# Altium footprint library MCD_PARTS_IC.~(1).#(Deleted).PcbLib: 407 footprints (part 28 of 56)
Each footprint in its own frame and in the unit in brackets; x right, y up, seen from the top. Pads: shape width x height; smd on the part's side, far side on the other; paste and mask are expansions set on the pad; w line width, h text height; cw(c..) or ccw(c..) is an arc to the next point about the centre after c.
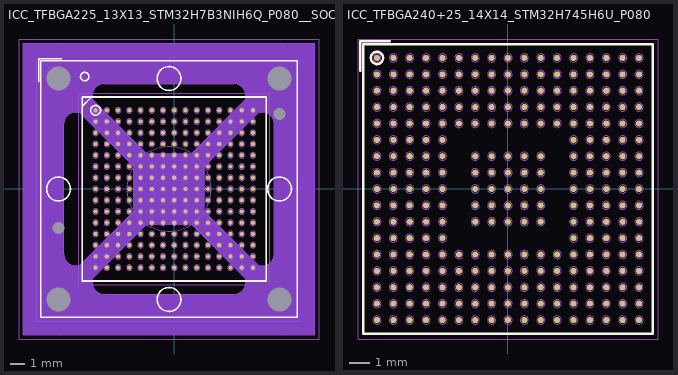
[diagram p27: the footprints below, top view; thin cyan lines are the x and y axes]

## ICC_TFBGA225_13X13_STM32H7B3NIH6Q_P080__SOCKET_IRONWOOD_CS1222291MF_REV-A_WITHOUT-3D-SOCKET [mm] "MCD-01577"
height 1.2
pads (231):
  round 0.3 smd mask+0.05: A1(-5.6,5.6) A2(-4.8,5.6) A3(-4,5.6) A4(-3.2,5.6) A5(-2.4,5.6) A6(-1.6,5.6) A7(-0.8,5.6) A8(0,5.6) A9(0.8,5.6) A10(1.6,5.6) A11(2.4,5.6) A12(3.2,5.6) A13(4,5.6) A14(4.8,5.6) A15(5.6,5.6) B1(-5.6,4.8) B2(-4.8,4.8) B3(-4,4.8) B4(-3.2,4.8) B5(-2.4,4.8) B6(-1.6,4.8) B7(-0.8,4.8) B8(0,4.8) B9(0.8,4.8) B10(1.6,4.8) B11(2.4,4.8) B12(3.2,4.8) B13(4,4.8) B14(4.8,4.8) B15(5.6,4.8) C1(-5.6,4) C2(-4.8,4) C3(-4,4) C4(-3.2,4) C5(-2.4,4) C6(-1.6,4) C7(-0.8,4) C8(0,4) C9(0.8,4) C10(1.6,4) C11(2.4,4) C12(3.2,4) C13(4,4) C14(4.8,4) C15(5.6,4) D1(-5.6,3.2) D2(-4.8,3.2) D3(-4,3.2) D4(-3.2,3.2) D5(-2.4,3.2) D6(-1.6,3.2) D7(-0.8,3.2) D8(0,3.2) D9(0.8,3.2) D10(1.6,3.2) D11(2.4,3.2) D12(3.2,3.2) D13(4,3.2) D14(4.8,3.2) D15(5.6,3.2) E1(-5.6,2.4) E2(-4.8,2.4) E3(-4,2.4) E4(-3.2,2.4) E5(-2.4,2.4) E6(-1.6,2.4) E7(-0.8,2.4) E8(0,2.4) E9(0.8,2.4) E10(1.6,2.4) E11(2.4,2.4) E12(3.2,2.4) E13(4,2.4) E14(4.8,2.4) E15(5.6,2.4) F1(-5.6,1.6) F2(-4.8,1.6) F3(-4,1.6) F4(-3.2,1.6) F5(-2.4,1.6) F6(-1.6,1.6) F7(-0.8,1.6) F8(0,1.6) F9(0.8,1.6) F10(1.6,1.6) F11(2.4,1.6) F12(3.2,1.6) F13(4,1.6) F14(4.8,1.6) F15(5.6,1.6) G1(-5.6,0.8) G2(-4.8,0.8) G3(-4,0.8) G4(-3.2,0.8) G5(-2.4,0.8) G6(-1.6,0.8) G7(-0.8,0.8) G8(0,0.8) G9(0.8,0.8) G10(1.6,0.8) G11(2.4,0.8) G12(3.2,0.8) G13(4,0.8) G14(4.8,0.8) G15(5.6,0.8) H1(-5.6,0) H2(-4.8,0) H3(-4,0) H4(-3.2,0) H5(-2.4,0) H6(-1.6,0) H7(-0.8,0) H8(0,0) H9(0.8,0) H10(1.6,0) H11(2.4,0) H12(3.2,0) H13(4,0) H14(4.8,0) H15(5.6,0) J1(-5.6,-0.8) J2(-4.8,-0.8) J3(-4,-0.8) J4(-3.2,-0.8) J5(-2.4,-0.8) J6(-1.6,-0.8) J7(-0.8,-0.8) J8(0,-0.8) J9(0.8,-0.8) J10(1.6,-0.8) J11(2.4,-0.8) J12(3.2,-0.8) J13(4,-0.8) J14(4.8,-0.8) J15(5.6,-0.8) K1(-5.6,-1.6) K2(-4.8,-1.6) K3(-4,-1.6) K4(-3.2,-1.6) K5(-2.4,-1.6) K6(-1.6,-1.6) K7(-0.8,-1.6) K8(0,-1.6) K9(0.8,-1.6) K10(1.6,-1.6) K11(2.4,-1.6) K12(3.2,-1.6) K13(4,-1.6) K14(4.8,-1.6) K15(5.6,-1.6) L1(-5.6,-2.4) L2(-4.8,-2.4) L3(-4,-2.4) L4(-3.2,-2.4) L5(-2.4,-2.4) L6(-1.6,-2.4) L7(-0.8,-2.4) L8(0,-2.4) L9(0.8,-2.4) L10(1.6,-2.4) L11(2.4,-2.4) L12(3.2,-2.4) L13(4,-2.4) L14(4.8,-2.4) L15(5.6,-2.4) M1(-5.6,-3.2) M2(-4.8,-3.2) M3(-4,-3.2) M4(-3.2,-3.2) M5(-2.4,-3.2) M6(-1.6,-3.2) M7(-0.8,-3.2) M8(0,-3.2) M9(0.8,-3.2) M10(1.6,-3.2) M11(2.4,-3.2) M12(3.2,-3.2) M13(4,-3.2) M14(4.8,-3.2) M15(5.6,-3.2) N1(-5.6,-4) N2(-4.8,-4) N3(-4,-4) N4(-3.2,-4) N5(-2.4,-4) N6(-1.6,-4) N7(-0.8,-4) N8(0,-4) N9(0.8,-4) N10(1.6,-4) N11(2.4,-4) N12(3.2,-4) N13(4,-4) N14(4.8,-4) N15(5.6,-4) P1(-5.6,-4.8) P2(-4.8,-4.8) P3(-4,-4.8) P4(-3.2,-4.8) P5(-2.4,-4.8) P6(-1.6,-4.8) P7(-0.8,-4.8) P8(0,-4.8) P9(0.8,-4.8) P10(1.6,-4.8) P11(2.4,-4.8) P12(3.2,-4.8) P13(4,-4.8) P14(4.8,-4.8) P15(5.6,-4.8) R1(-5.6,-5.6) R2(-4.8,-5.6) R3(-4,-5.6) R4(-3.2,-5.6) R5(-2.4,-5.6) R6(-1.6,-5.6) R7(-0.8,-5.6) R8(0,-5.6) R9(0.8,-5.6) R10(1.6,-5.6) R11(2.4,-5.6) R12(3.2,-5.6) R13(4,-5.6) R14(4.8,-5.6) R15(5.6,-5.6)
  round 0 hole 0.85 unplated mask+0.05: NPTH1(7.487,5.322) NPTH2(-8.238,-2.783)
  round 0 hole 1.71 unplated mask+0.05: PTH1(-8.238,7.862) PTH2(7.487,7.862) PTH3(7.487,-7.863) PTH4(-8.238,-7.863)
Bottom Layer keep-out:
  circle w0.01: c7.487,7.862 r2.5
  circle w0.01: c-8.238,7.862 r2.5
  circle w0.01: c-8.238,-7.863 r2.5
  circle w0.01: c7.487,-7.863 r2.5
  region: -0.376,0 -0.376,-2.5 1.224,-2.5 5.024,-6.3 5.04,-6.317 5.066,-6.356 5.084,-6.4 5.093,-6.446 5.094,-6.469 5.094,-6.63 5.09,-6.715 5.057,-6.883 4.991,-7.04 4.897,-7.182 4.776,-7.303 4.634,-7.397 4.477,-7.463 4.309,-7.496 4.224,-7.5 -0.376,-7.5 -0.376,-10.365 9.988,-10.365 9.988,10.365 -0.376,10.365 -0.376,7.5 4.224,7.5 4.309,7.496 4.477,7.463 4.634,7.397 4.776,7.303 4.897,7.182 4.991,7.04 5.057,6.883 5.09,6.715 5.094,6.63 5.094,6.469 5.093,6.446 5.084,6.4 5.066,6.356 5.04,6.317 5.024,6.3 1.224,2.5 -0.376,2.5 -0.376,0 2.124,0 2.124,1.6 5.924,5.4 5.941,5.416 5.98,5.442 6.024,5.46 6.07,5.469 6.093,5.47 6.254,5.47 6.339,5.466 6.507,5.433 6.664,5.367 6.806,5.273 6.927,5.152 7.021,5.01 7.087,4.853 7.12,4.685 7.124,4.6 7.124,-4.6 7.12,-4.685 7.087,-4.853 7.021,-5.01 6.927,-5.152 6.806,-5.273 6.664,-5.367 6.507,-5.433 6.339,-5.466 6.254,-5.47 6.093,-5.47 6.07,-5.469 6.024,-5.46 5.98,-5.442 5.941,-5.416 5.924,-5.4 2.124,-1.6 2.124,0
  region: -0.376,0 -0.376,2.5 -1.976,2.5 -5.776,6.3 -5.792,6.317 -5.818,6.356 -5.836,6.4 -5.845,6.446 -5.846,6.469 -5.846,6.63 -5.842,6.715 -5.809,6.883 -5.743,7.04 -5.649,7.182 -5.528,7.303 -5.386,7.397 -5.229,7.463 -5.061,7.496 -4.976,7.5 -0.376,7.5 -0.376,10.365 -10.74,10.365 -10.74,-10.365 -0.376,-10.365 -0.376,-7.5 -4.976,-7.5 -5.061,-7.496 -5.229,-7.463 -5.386,-7.397 -5.528,-7.303 -5.649,-7.182 -5.743,-7.04 -5.809,-6.883 -5.842,-6.715 -5.846,-6.63 -5.846,-6.469 -5.845,-6.446 -5.836,-6.4 -5.818,-6.356 -5.792,-6.317 -5.776,-6.3 -1.976,-2.5 -0.376,-2.5 -0.376,0 -2.876,0 -2.876,-1.6 -6.676,-5.4 -6.693,-5.416 -6.732,-5.442 -6.776,-5.46 -6.822,-5.469 -6.845,-5.47 -7.006,-5.47 -7.091,-5.466 -7.259,-5.433 -7.416,-5.367 -7.558,-5.273 -7.679,-5.152 -7.773,-5.01 -7.839,-4.853 -7.872,-4.685 -7.876,-4.6 -7.876,4.6 -7.872,4.685 -7.839,4.853 -7.773,5.01 -7.679,5.152 -7.558,5.273 -7.416,5.367 -7.259,5.433 -7.091,5.466 -7.006,5.47 -6.845,5.47 -6.822,5.469 -6.776,5.46 -6.732,5.442 -6.693,5.416 -6.676,5.4 -2.876,1.6 -2.876,0
Top Overlay:
  circle w0.12: c-6.375,8 r0.3
  circle w0.12: c-0.375,-7.863 r0.85
  circle w0.12: c7.487,0 r0.85
  circle w0.12: c-0.375,7.862 r0.85
  circle w0.12: c-8.238,0 r0.85
  circle w0.12: c-5.6,5.6 r0.35
  lines w0.12: -9.65,7.625 -9.65,9.275 -8,9.275 ; -6.55,5.895 -5.895,6.55 ; -9.5,-9.125 8.75,-9.125 8.75,9.125 -9.5,9.125 -9.5,-9.125 ; -6.55,-6.55 -6.55,6.55 6.55,6.55 6.55,-6.55 -6.55,-6.55
Bottom Overlay:
  lines w0.12: -10.75,-10.375 10,-10.375 10,10.375 -7.625,10.375 -10.75,10.375 -10.75,-10.375
M14-Top Assembly:
  drawing of 245 lines, arcs and shapes, not listed
  text "A1" at -5.85,5.425 h0.4
  text "'.Designator'" at -6.5,7.25 h0.75
M15-Bottom Assembly:
  lines w0.01: -2.891,1.615 -2.876,1.6 ; -2.891,1.615 -6.676,5.4 ccw(c-6.845,5.231) -6.845,5.47 -7.006,5.47 ccw(c-7.006,4.6) -7.876,4.6 -7.876,-4.6 ccw(c-7.006,-4.6) -7.006,-5.47 -6.845,-5.47 ccw(c-6.845,-5.231) -6.676,-5.4 -2.891,-1.615 -2.876,-1.6 -2.876,1.6 ; -2.891,1.615 -2.891,1.615 ; -2.876,1.6 -2.876,1.6 ; -1.991,-2.515 -1.991,-2.515 ; -1.991,-2.515 -5.776,-6.3 ccw(c-5.607,-6.469) -5.846,-6.469 -5.846,-6.63 ccw(c-4.976,-6.63) -4.976,-7.5 4.224,-7.5 ccw(c4.224,-6.63) 5.094,-6.63 5.094,-6.469 ccw(c4.855,-6.469) 5.024,-6.3 1.239,-2.515 1.224,-2.5 -1.976,-2.5 ; -1.991,-2.515 -1.976,-2.5 ; -1.976,-2.5 -1.976,-2.5 ; 1.224,2.5 1.239,2.515 ; 1.224,2.5 1.224,2.5 ; 1.224,2.5 -1.976,2.5 -1.991,2.515 -5.776,6.3 cw(c-5.607,6.469) -5.846,6.469 -5.846,6.63 cw(c-4.976,6.63) -4.976,7.5 4.224,7.5 cw(c4.224,6.63) 5.094,6.63 5.094,6.469 cw(c4.855,6.469) 5.024,6.3 1.239,2.515 ; 1.239,2.515 1.239,2.515 ; 2.124,-1.6 2.139,-1.615 ; 2.124,-1.6 2.124,-1.6 ; 2.124,-1.6 2.124,1.6 2.139,1.615 5.924,5.4 cw(c6.093,5.231) 6.093,5.47 6.254,5.47 cw(c6.254,4.6) 7.124,4.6 7.124,-4.6 cw(c6.254,-4.6) 6.254,-5.47 6.093,-5.47 cw(c6.093,-5.231) 5.924,-5.4 2.139,-1.615 ; 2.139,-1.615 2.139,-1.615 ; -10.74,-10.365 -10.74,10.365 9.99,10.365 9.99,-10.365 -10.74,-10.365
M16-Top Courtyard:
  lines w0.01: -9.8,-9.425 -9.8,8.5 -9.8,9.425 9.05,9.425 9.05,-9.425 -9.8,-9.425 ; -6.8,-6.8 6.8,-6.8 6.8,6.8 -6.8,6.8 -6.8,-6.8
M17-Bottom Courtyard:
  lines w0.01: -11.05,-10.675 10.3,-10.675 10.3,10.675 -11.05,10.675 -11.05,-10.675
3D body: height 0.36, standoff -0.04, extent 5.401,5.403 5.8,5.797
3D body: height 1.2, standoff 0.3, extent -6.55,-6.55 6.55,6.55
3D body: height 0.36, standoff -0.04, extent 4.601,5.403 5,5.797
3D body: height 0.36, standoff -0.04, extent 3.801,5.403 4.2,5.797
3D body: height 0.36, standoff -0.04, extent 3.001,5.403 3.4,5.797
3D body: height 0.36, standoff -0.04, extent 2.201,5.403 2.6,5.797
3D body: height 0.36, standoff -0.04, extent -1.799,5.403 -1.4,5.797
3D body: height 0.36, standoff -0.04, extent -0.999,5.403 -0.6,5.797
3D body: height 0.36, standoff -0.04, extent -0.199,5.403 0.2,5.797
3D body: height 0.36, standoff -0.04, extent 0.601,5.403 1,5.797
3D body: height 0.36, standoff -0.04, extent 1.401,5.403 1.8,5.797
3D body: height 0.36, standoff -0.04, extent -5.799,5.403 -5.4,5.797
3D body: height 0.36, standoff -0.04, extent -4.999,5.403 -4.6,5.797
3D body: height 0.36, standoff -0.04, extent -4.199,5.403 -3.8,5.797
3D body: height 0.36, standoff -0.04, extent -3.399,5.403 -3,5.797
3D body: height 0.36, standoff -0.04, extent -2.599,5.403 -2.2,5.797
3D body: height 0.36, standoff -0.04, extent -2.599,4.603 -2.2,4.997
3D body: height 0.36, standoff -0.04, extent -3.399,4.603 -3,4.997
3D body: height 0.36, standoff -0.04, extent -4.199,4.603 -3.8,4.997
3D body: height 0.36, standoff -0.04, extent -4.999,4.603 -4.6,4.997
3D body: height 0.36, standoff -0.04, extent -5.799,4.603 -5.4,4.997
3D body: height 0.36, standoff -0.04, extent 1.401,4.603 1.8,4.997
3D body: height 0.36, standoff -0.04, extent 0.601,4.603 1,4.997
3D body: height 0.36, standoff -0.04, extent -0.199,4.603 0.2,4.997
3D body: height 0.36, standoff -0.04, extent -0.999,4.603 -0.6,4.997
3D body: height 0.36, standoff -0.04, extent -1.799,4.603 -1.4,4.997
3D body: height 0.36, standoff -0.04, extent 2.201,4.603 2.6,4.997
3D body: height 0.36, standoff -0.04, extent 3.001,4.603 3.4,4.997
3D body: height 0.36, standoff -0.04, extent 3.801,4.603 4.2,4.997
3D body: height 0.36, standoff -0.04, extent 4.601,4.603 5,4.997
3D body: height 0.36, standoff -0.04, extent 5.401,4.603 5.8,4.997
3D body: height 0.36, standoff -0.04, extent -2.599,3.803 -2.2,4.197
3D body: height 0.36, standoff -0.04, extent -3.399,3.803 -3,4.197
3D body: height 0.36, standoff -0.04, extent -4.199,3.803 -3.8,4.197
3D body: height 0.36, standoff -0.04, extent -4.999,3.803 -4.6,4.197
3D body: height 0.36, standoff -0.04, extent -5.799,3.803 -5.4,4.197
3D body: height 0.36, standoff -0.04, extent 1.401,3.803 1.8,4.197
3D body: height 0.36, standoff -0.04, extent 0.601,3.803 1,4.197
3D body: height 0.36, standoff -0.04, extent -0.199,3.803 0.2,4.197
3D body: height 0.36, standoff -0.04, extent -0.999,3.803 -0.6,4.197
3D body: height 0.36, standoff -0.04, extent -1.799,3.803 -1.4,4.197
3D body: height 0.36, standoff -0.04, extent 2.201,3.803 2.6,4.197
3D body: height 0.36, standoff -0.04, extent 3.001,3.803 3.4,4.197
3D body: height 0.36, standoff -0.04, extent 3.801,3.803 4.2,4.197
3D body: height 0.36, standoff -0.04, extent 4.601,3.803 5,4.197
3D body: height 0.36, standoff -0.04, extent 5.401,3.803 5.8,4.197
3D body: height 0.36, standoff -0.04, extent -2.599,3.003 -2.2,3.397
3D body: height 0.36, standoff -0.04, extent -3.399,3.003 -3,3.397
3D body: height 0.36, standoff -0.04, extent -4.199,3.003 -3.8,3.397
3D body: height 0.36, standoff -0.04, extent -4.999,3.003 -4.6,3.397
3D body: height 0.36, standoff -0.04, extent -5.799,3.003 -5.4,3.397
3D body: height 0.36, standoff -0.04, extent 1.401,3.003 1.8,3.397
3D body: height 0.36, standoff -0.04, extent 0.601,3.003 1,3.397
3D body: height 0.36, standoff -0.04, extent -0.199,3.003 0.2,3.397
3D body: height 0.36, standoff -0.04, extent -0.999,3.003 -0.6,3.397
3D body: height 0.36, standoff -0.04, extent -1.799,3.003 -1.4,3.397
3D body: height 0.36, standoff -0.04, extent 2.201,3.003 2.6,3.397
3D body: height 0.36, standoff -0.04, extent 3.001,3.003 3.4,3.397
3D body: height 0.36, standoff -0.04, extent 3.801,3.003 4.2,3.397
3D body: height 0.36, standoff -0.04, extent 4.601,3.003 5,3.397
3D body: height 0.36, standoff -0.04, extent 5.401,3.003 5.8,3.397
3D body: height 0.36, standoff -0.04, extent -2.599,2.203 -2.2,2.597
3D body: height 0.36, standoff -0.04, extent -3.399,2.203 -3,2.597
3D body: height 0.36, standoff -0.04, extent -4.199,2.203 -3.8,2.597
3D body: height 0.36, standoff -0.04, extent -4.999,2.203 -4.6,2.597
3D body: height 0.36, standoff -0.04, extent -5.799,2.203 -5.4,2.597
3D body: height 0.36, standoff -0.04, extent 1.401,2.203 1.8,2.597
3D body: height 0.36, standoff -0.04, extent 0.601,2.203 1,2.597
3D body: height 0.36, standoff -0.04, extent -0.199,2.203 0.2,2.597
3D body: height 0.36, standoff -0.04, extent -0.999,2.203 -0.6,2.597
3D body: height 0.36, standoff -0.04, extent -1.799,2.203 -1.4,2.597
3D body: height 0.36, standoff -0.04, extent 2.201,2.203 2.6,2.597
3D body: height 0.36, standoff -0.04, extent 3.001,2.203 3.4,2.597
3D body: height 0.36, standoff -0.04, extent 3.801,2.203 4.2,2.597
3D body: height 0.36, standoff -0.04, extent 4.601,2.203 5,2.597
3D body: height 0.36, standoff -0.04, extent 5.401,2.203 5.8,2.597
3D body: height 0.36, standoff -0.04, extent -2.599,1.403 -2.2,1.797
3D body: height 0.36, standoff -0.04, extent -3.399,1.403 -3,1.797
3D body: height 0.36, standoff -0.04, extent -4.199,1.403 -3.8,1.797
3D body: height 0.36, standoff -0.04, extent -4.999,1.403 -4.6,1.797
3D body: height 0.36, standoff -0.04, extent -5.799,1.403 -5.4,1.797
3D body: height 0.36, standoff -0.04, extent 1.401,1.403 1.8,1.797
3D body: height 0.36, standoff -0.04, extent 0.601,1.403 1,1.797
3D body: height 0.36, standoff -0.04, extent -0.199,1.403 0.2,1.797
3D body: height 0.36, standoff -0.04, extent -0.999,1.403 -0.6,1.797
3D body: height 0.36, standoff -0.04, extent -1.799,1.403 -1.4,1.797
3D body: height 0.36, standoff -0.04, extent 2.201,1.403 2.6,1.797
3D body: height 0.36, standoff -0.04, extent 3.001,1.403 3.4,1.797
3D body: height 0.36, standoff -0.04, extent 3.801,1.403 4.2,1.797
3D body: height 0.36, standoff -0.04, extent 4.601,1.403 5,1.797
3D body: height 0.36, standoff -0.04, extent 5.401,1.403 5.8,1.797
3D body: height 0.36, standoff -0.04, extent -2.599,0.603 -2.2,0.997
3D body: height 0.36, standoff -0.04, extent -3.399,0.603 -3,0.997
3D body: height 0.36, standoff -0.04, extent -4.199,0.603 -3.8,0.997
3D body: height 0.36, standoff -0.04, extent -4.999,0.603 -4.6,0.997
3D body: height 0.36, standoff -0.04, extent -5.799,0.603 -5.4,0.997
3D body: height 0.36, standoff -0.04, extent 1.401,0.603 1.8,0.997
3D body: height 0.36, standoff -0.04, extent 0.601,0.603 1,0.997
3D body: height 0.36, standoff -0.04, extent -0.199,0.603 0.2,0.997
3D body: height 0.36, standoff -0.04, extent -0.999,0.603 -0.6,0.997
3D body: height 0.36, standoff -0.04, extent -1.799,0.603 -1.4,0.997
3D body: height 0.36, standoff -0.04, extent 2.201,0.603 2.6,0.997
3D body: height 0.36, standoff -0.04, extent 3.001,0.603 3.4,0.997
3D body: height 0.36, standoff -0.04, extent 3.801,0.603 4.2,0.997
3D body: height 0.36, standoff -0.04, extent 4.601,0.603 5,0.997
3D body: height 0.36, standoff -0.04, extent 5.401,0.603 5.8,0.997
3D body: height 0.36, standoff -0.04, extent -2.599,-0.197 -2.2,0.197
3D body: height 0.36, standoff -0.04, extent -3.399,-0.197 -3,0.197
3D body: height 0.36, standoff -0.04, extent -4.199,-0.197 -3.8,0.197
3D body: height 0.36, standoff -0.04, extent -4.999,-0.197 -4.6,0.197
3D body: height 0.36, standoff -0.04, extent -5.799,-0.197 -5.4,0.197
3D body: height 0.36, standoff -0.04, extent 1.401,-0.197 1.8,0.197
3D body: height 0.36, standoff -0.04, extent 0.601,-0.197 1,0.197
3D body: height 0.36, standoff -0.04, extent -0.199,-0.197 0.2,0.197
3D body: height 0.36, standoff -0.04, extent -0.999,-0.197 -0.6,0.197
3D body: height 0.36, standoff -0.04, extent -1.799,-0.197 -1.4,0.197
3D body: height 0.36, standoff -0.04, extent 2.201,-0.197 2.6,0.197
3D body: height 0.36, standoff -0.04, extent 3.001,-0.197 3.4,0.197
3D body: height 0.36, standoff -0.04, extent 3.801,-0.197 4.2,0.197
3D body: height 0.36, standoff -0.04, extent 4.601,-0.197 5,0.197
3D body: height 0.36, standoff -0.04, extent 5.401,-0.197 5.8,0.197
3D body: height 0.36, standoff -0.04, extent -2.599,-0.997 -2.2,-0.603
3D body: height 0.36, standoff -0.04, extent -3.399,-0.997 -3,-0.603
3D body: height 0.36, standoff -0.04, extent -4.199,-0.997 -3.8,-0.603
3D body: height 0.36, standoff -0.04, extent -4.999,-0.997 -4.6,-0.603
3D body: height 0.36, standoff -0.04, extent -5.799,-0.997 -5.4,-0.603
3D body: height 0.36, standoff -0.04, extent 1.401,-0.997 1.8,-0.603
3D body: height 0.36, standoff -0.04, extent 0.601,-0.997 1,-0.603
3D body: height 0.36, standoff -0.04, extent -0.199,-0.997 0.2,-0.603
3D body: height 0.36, standoff -0.04, extent -0.999,-0.997 -0.6,-0.603
3D body: height 0.36, standoff -0.04, extent -1.799,-0.997 -1.4,-0.603
3D body: height 0.36, standoff -0.04, extent 2.201,-0.997 2.6,-0.603
3D body: height 0.36, standoff -0.04, extent 3.001,-0.997 3.4,-0.603
3D body: height 0.36, standoff -0.04, extent 3.801,-0.997 4.2,-0.603
3D body: height 0.36, standoff -0.04, extent 4.601,-0.997 5,-0.603
3D body: height 0.36, standoff -0.04, extent 5.401,-0.997 5.8,-0.603
3D body: height 0.36, standoff -0.04, extent -2.599,-1.797 -2.2,-1.403
3D body: height 0.36, standoff -0.04, extent -3.399,-1.797 -3,-1.403
3D body: height 0.36, standoff -0.04, extent -4.199,-1.797 -3.8,-1.403
3D body: height 0.36, standoff -0.04, extent -4.999,-1.797 -4.6,-1.403
3D body: height 0.36, standoff -0.04, extent -5.799,-1.797 -5.4,-1.403
3D body: height 0.36, standoff -0.04, extent 1.401,-1.797 1.8,-1.403
3D body: height 0.36, standoff -0.04, extent 0.601,-1.797 1,-1.403
3D body: height 0.36, standoff -0.04, extent -0.199,-1.797 0.2,-1.403
3D body: height 0.36, standoff -0.04, extent -0.999,-1.797 -0.6,-1.403
3D body: height 0.36, standoff -0.04, extent -1.799,-1.797 -1.4,-1.403
3D body: height 0.36, standoff -0.04, extent 2.201,-1.797 2.6,-1.403
3D body: height 0.36, standoff -0.04, extent 3.001,-1.797 3.4,-1.403
3D body: height 0.36, standoff -0.04, extent 3.801,-1.797 4.2,-1.403
3D body: height 0.36, standoff -0.04, extent 4.601,-1.797 5,-1.403
3D body: height 0.36, standoff -0.04, extent 5.401,-1.797 5.8,-1.403
3D body: height 0.36, standoff -0.04, extent -2.599,-2.597 -2.2,-2.203
3D body: height 0.36, standoff -0.04, extent -3.399,-2.597 -3,-2.203
3D body: height 0.36, standoff -0.04, extent -4.199,-2.597 -3.8,-2.203
3D body: height 0.36, standoff -0.04, extent -4.999,-2.597 -4.6,-2.203
3D body: height 0.36, standoff -0.04, extent -5.799,-2.597 -5.4,-2.203
3D body: height 0.36, standoff -0.04, extent 1.401,-2.597 1.8,-2.203
3D body: height 0.36, standoff -0.04, extent 0.601,-2.597 1,-2.203
3D body: height 0.36, standoff -0.04, extent -0.199,-2.597 0.2,-2.203
3D body: height 0.36, standoff -0.04, extent -0.999,-2.597 -0.6,-2.203
3D body: height 0.36, standoff -0.04, extent -1.799,-2.597 -1.4,-2.203
3D body: height 0.36, standoff -0.04, extent 2.201,-2.597 2.6,-2.203
3D body: height 0.36, standoff -0.04, extent 3.001,-2.597 3.4,-2.203
3D body: height 0.36, standoff -0.04, extent 3.801,-2.597 4.2,-2.203
3D body: height 0.36, standoff -0.04, extent 4.601,-2.597 5,-2.203
3D body: height 0.36, standoff -0.04, extent 5.401,-2.597 5.8,-2.203
3D body: height 0.36, standoff -0.04, extent -2.599,-3.397 -2.2,-3.003
3D body: height 0.36, standoff -0.04, extent -3.399,-3.397 -3,-3.003
3D body: height 0.36, standoff -0.04, extent -4.199,-3.397 -3.8,-3.003
3D body: height 0.36, standoff -0.04, extent -4.999,-3.397 -4.6,-3.003
3D body: height 0.36, standoff -0.04, extent -5.799,-3.397 -5.4,-3.003
3D body: height 0.36, standoff -0.04, extent 1.401,-3.397 1.8,-3.003
3D body: height 0.36, standoff -0.04, extent 0.601,-3.397 1,-3.003
3D body: height 0.36, standoff -0.04, extent -0.199,-3.397 0.2,-3.003
3D body: height 0.36, standoff -0.04, extent -0.999,-3.397 -0.6,-3.003
3D body: height 0.36, standoff -0.04, extent -1.799,-3.397 -1.4,-3.003
3D body: height 0.36, standoff -0.04, extent 2.201,-3.397 2.6,-3.003
3D body: height 0.36, standoff -0.04, extent 3.001,-3.397 3.4,-3.003
3D body: height 0.36, standoff -0.04, extent 3.801,-3.397 4.2,-3.003
3D body: height 0.36, standoff -0.04, extent 4.601,-3.397 5,-3.003
3D body: height 0.36, standoff -0.04, extent 5.401,-3.397 5.8,-3.003
3D body: height 0.36, standoff -0.04, extent -2.599,-4.197 -2.2,-3.803
3D body: height 0.36, standoff -0.04, extent -3.399,-4.197 -3,-3.803
3D body: height 0.36, standoff -0.04, extent -4.199,-4.197 -3.8,-3.803
3D body: height 0.36, standoff -0.04, extent -4.999,-4.197 -4.6,-3.803
3D body: height 0.36, standoff -0.04, extent -5.799,-4.197 -5.4,-3.803
3D body: height 0.36, standoff -0.04, extent 1.401,-4.197 1.8,-3.803
3D body: height 0.36, standoff -0.04, extent 0.601,-4.197 1,-3.803
3D body: height 0.36, standoff -0.04, extent -0.199,-4.197 0.2,-3.803
3D body: height 0.36, standoff -0.04, extent -0.999,-4.197 -0.6,-3.803
3D body: height 0.36, standoff -0.04, extent -1.799,-4.197 -1.4,-3.803
3D body: height 0.36, standoff -0.04, extent 2.201,-4.197 2.6,-3.803
3D body: height 0.36, standoff -0.04, extent 3.001,-4.197 3.4,-3.803
3D body: height 0.36, standoff -0.04, extent 3.801,-4.197 4.2,-3.803
3D body: height 0.36, standoff -0.04, extent 4.601,-4.197 5,-3.803
3D body: height 0.36, standoff -0.04, extent 5.401,-4.197 5.8,-3.803
3D body: height 0.36, standoff -0.04, extent -2.599,-4.997 -2.2,-4.603
3D body: height 0.36, standoff -0.04, extent -3.399,-4.997 -3,-4.603
3D body: height 0.36, standoff -0.04, extent -4.199,-4.997 -3.8,-4.603
3D body: height 0.36, standoff -0.04, extent -4.999,-4.997 -4.6,-4.603
3D body: height 0.36, standoff -0.04, extent -5.799,-4.997 -5.4,-4.603
3D body: height 0.36, standoff -0.04, extent 1.401,-4.997 1.8,-4.603
3D body: height 0.36, standoff -0.04, extent 0.601,-4.997 1,-4.603
3D body: height 0.36, standoff -0.04, extent -0.199,-4.997 0.2,-4.603
3D body: height 0.36, standoff -0.04, extent -0.999,-4.997 -0.6,-4.603
3D body: height 0.36, standoff -0.04, extent -1.799,-4.997 -1.4,-4.603
3D body: height 0.36, standoff -0.04, extent 2.201,-4.997 2.6,-4.603
3D body: height 0.36, standoff -0.04, extent 3.001,-4.997 3.4,-4.603
3D body: height 0.36, standoff -0.04, extent 3.801,-4.997 4.2,-4.603
3D body: height 0.36, standoff -0.04, extent 4.601,-4.997 5,-4.603
3D body: height 0.36, standoff -0.04, extent 5.401,-4.997 5.8,-4.603
3D body: height 0.36, standoff -0.04, extent -2.599,-5.797 -2.2,-5.403
3D body: height 0.36, standoff -0.04, extent -3.399,-5.797 -3,-5.403
3D body: height 0.36, standoff -0.04, extent -4.199,-5.797 -3.8,-5.403
3D body: height 0.36, standoff -0.04, extent -4.999,-5.797 -4.6,-5.403
3D body: height 0.36, standoff -0.04, extent -5.799,-5.797 -5.4,-5.403
3D body: height 0.36, standoff -0.04, extent 1.401,-5.797 1.8,-5.403
3D body: height 0.36, standoff -0.04, extent 0.601,-5.797 1,-5.403
3D body: height 0.36, standoff -0.04, extent -0.199,-5.797 0.2,-5.403
3D body: height 0.36, standoff -0.04, extent -0.999,-5.797 -0.6,-5.403
3D body: height 0.36, standoff -0.04, extent -1.799,-5.797 -1.4,-5.403
3D body: height 0.36, standoff -0.04, extent 2.201,-5.797 2.6,-5.403
3D body: height 0.36, standoff -0.04, extent 3.001,-5.797 3.4,-5.403
3D body: height 0.36, standoff -0.04, extent 3.801,-5.797 4.2,-5.403
3D body: height 0.36, standoff -0.04, extent 4.601,-5.797 5,-5.403
3D body: height 0.36, standoff -0.04, extent 5.401,-5.797 5.8,-5.403
3D body: height 1.21, standoff 1.2, extent -5.897,5.301 -5.3,5.9

## ICC_TFBGA240+25_14X14_STM32H745H6U_P080 [mm]
height 1.1
pads (265):
  round 0.3 smd mask+0.05: A1(-6.4,6.4) A2(-5.6,6.4) A3(-4.8,6.4) A4(-4,6.4) A5(-3.2,6.4) A6(-2.4,6.4) A7(-1.6,6.4) A8(-0.8,6.4) A9(0,6.4) A10(0.8,6.4) A11(1.6,6.4) A12(2.4,6.4) A13(3.2,6.4) A14(4,6.4) A15(4.8,6.4) A16(5.6,6.4) A17(6.4,6.4) B1(-6.4,5.6) B2(-5.6,5.6) B3(-4.8,5.6) B4(-4,5.6) B5(-3.2,5.6) B6(-2.4,5.6) B7(-1.6,5.6) B8(-0.8,5.6) B9(0,5.6) B10(0.8,5.6) B11(1.6,5.6) B12(2.4,5.6) B13(3.2,5.6) B14(4,5.6) B15(4.8,5.6) B16(5.6,5.6) B17(6.4,5.6) C1(-6.4,4.8) C2(-5.6,4.8) C3(-4.8,4.8) C4(-4,4.8) C5(-3.2,4.8) C6(-2.4,4.8) C7(-1.6,4.8) C8(-0.8,4.8) C9(0,4.8) C10(0.8,4.8) C11(1.6,4.8) C12(2.4,4.8) C13(3.2,4.8) C14(4,4.8) C15(4.8,4.8) C16(5.6,4.8) C17(6.4,4.8) D1(-6.4,4) D2(-5.6,4) D3(-4.8,4) D4(-4,4) D5(-3.2,4) D6(-2.4,4) D7(-1.6,4) D8(-0.8,4) D9(0,4) D10(0.8,4) D11(1.6,4) D12(2.4,4) D13(3.2,4) D14(4,4) D15(4.8,4) D16(5.6,4) D17(6.4,4) E1(-6.4,3.2) E2(-5.6,3.2) E3(-4.8,3.2) E4(-4,3.2) E5(-3.2,3.2) E6(-2.4,3.2) E7(-1.6,3.2) E8(-0.8,3.2) E9(0,3.2) E10(0.8,3.2) E11(1.6,3.2) E12(2.4,3.2) E13(3.2,3.2) E14(4,3.2) E15(4.8,3.2) E16(5.6,3.2) E17(6.4,3.2) F1(-6.4,2.4) F2(-5.6,2.4) F3(-4.8,2.4) F4(-4,2.4) F5(-3.2,2.4) F13(3.2,2.4) F14(4,2.4) F15(4.8,2.4) F16(5.6,2.4) F17(6.4,2.4) G1(-6.4,1.6) G2(-5.6,1.6) G3(-4.8,1.6) G4(-4,1.6) G5(-3.2,1.6) G7(-1.6,1.6) G8(-0.8,1.6) G9(0,1.6) G10(0.8,1.6) G11(1.6,1.6) G13(3.2,1.6) G14(4,1.6) G15(4.8,1.6) G16(5.6,1.6) G17(6.4,1.6) H1(-6.4,0.8) H2(-5.6,0.8) H3(-4.8,0.8) H4(-4,0.8) H5(-3.2,0.8) H7(-1.6,0.8) H8(-0.8,0.8) H9(0,0.8) H10(0.8,0.8) H11(1.6,0.8) H13(3.2,0.8) H14(4,0.8) H15(4.8,0.8) H16(5.6,0.8) H17(6.4,0.8) J1(-6.4,0) J2(-5.6,0) J3(-4.8,0) J4(-4,0) J5(-3.2,0) J7(-1.6,0) J8(-0.8,0) J9(0,0) J10(0.8,0) J11(1.6,0) J13(3.2,0) J14(4,0) J15(4.8,0) J16(5.6,0) J17(6.4,0) K1(-6.4,-0.8) K2(-5.6,-0.8) K3(-4.8,-0.8) K4(-4,-0.8) K5(-3.2,-0.8) K7(-1.6,-0.8) K8(-0.8,-0.8) K9(0,-0.8) K10(0.8,-0.8) K11(1.6,-0.8) K13(3.2,-0.8) K14(4,-0.8) K15(4.8,-0.8) K16(5.6,-0.8) K17(6.4,-0.8) L1(-6.4,-1.6) L2(-5.6,-1.6) L3(-4.8,-1.6) L4(-4,-1.6) L5(-3.2,-1.6) L7(-1.6,-1.6) L8(-0.8,-1.6) L9(0,-1.6) L10(0.8,-1.6) L11(1.6,-1.6) L13(3.2,-1.6) L14(4,-1.6) L15(4.8,-1.6) L16(5.6,-1.6) L17(6.4,-1.6) M1(-6.4,-2.4) M2(-5.6,-2.4) M3(-4.8,-2.4) M4(-4,-2.4) M5(-3.2,-2.4) M13(3.2,-2.4) M14(4,-2.4) M15(4.8,-2.4) M16(5.6,-2.4) M17(6.4,-2.4) N1(-6.4,-3.2) N2(-5.6,-3.2) N3(-4.8,-3.2) N4(-4,-3.2) N5(-3.2,-3.2) N6(-2.4,-3.2) N7(-1.6,-3.2) N8(-0.8,-3.2) N9(0,-3.2) N10(0.8,-3.2) N11(1.6,-3.2) N12(2.4,-3.2) N13(3.2,-3.2) N14(4,-3.2) N15(4.8,-3.2) N16(5.6,-3.2) N17(6.4,-3.2) P1(-6.4,-4) P2(-5.6,-4) P3(-4.8,-4) P4(-4,-4) P5(-3.2,-4) P6(-2.4,-4) P7(-1.6,-4) P8(-0.8,-4) P9(0,-4) P10(0.8,-4) P11(1.6,-4) P12(2.4,-4) P13(3.2,-4) P14(4,-4) P15(4.8,-4) P16(5.6,-4) P17(6.4,-4) Q1(-6.4,-4.8) Q2(-5.6,-4.8) Q3(-4.8,-4.8) Q4(-4,-4.8) Q5(-3.2,-4.8) Q6(-2.4,-4.8) Q7(-1.6,-4.8) Q8(-0.8,-4.8) Q9(0,-4.8) Q10(0.8,-4.8) Q11(1.6,-4.8) Q12(2.4,-4.8) Q13(3.2,-4.8) Q14(4,-4.8) Q15(4.8,-4.8) Q16(5.6,-4.8) Q17(6.4,-4.8) R1(-6.4,-5.6) R2(-5.6,-5.6) R3(-4.8,-5.6) R4(-4,-5.6) R5(-3.2,-5.6) R6(-2.4,-5.6) R7(-1.6,-5.6) R8(-0.8,-5.6) R9(0,-5.6) R10(0.8,-5.6) R11(1.6,-5.6) R12(2.4,-5.6) R13(3.2,-5.6) R14(4,-5.6) R15(4.8,-5.6) R16(5.6,-5.6) R17(6.4,-5.6) S1(-6.4,-6.4) S2(-5.6,-6.4) S3(-4.8,-6.4) S4(-4,-6.4) S5(-3.2,-6.4) S6(-2.4,-6.4) S7(-1.6,-6.4) S8(-0.8,-6.4) S9(0,-6.4) S10(0.8,-6.4) S11(1.6,-6.4) S12(2.4,-6.4) S13(3.2,-6.4) S14(4,-6.4) S15(4.8,-6.4) S16(5.6,-6.4) S17(6.4,-6.4)
Top Overlay:
  circle w0.12: c-6.4,6.4 r0.3
  lines w0.12: -7.225,5.775 -7.225,7.225 -5.775,7.225 ; -7.075,-7.075 7.075,-7.075 7.075,7.075 -7.075,7.075 -7.075,-7.075
M14-Top Assembly:
  drawing of 269 lines, arcs and shapes, not listed
  text "'.Designator'" at -2,6.25 h0.75
  text "A1" at -6.65,6.225 h0.4
M16-Top Courtyard:
  lines w0.01: -7.325,-7.325 7.325,-7.325 7.325,7.325 -7.325,7.325 -7.325,-7.325
3D body: height 0.36, standoff -0.04, extent 4.601,-6.597 5,-6.203
3D body: height 0.36, standoff -0.04, extent 3.801,-6.597 4.2,-6.203
3D body: height 0.36, standoff -0.04, extent 3.001,-6.597 3.4,-6.203
3D body: height 0.36, standoff -0.04, extent 2.201,-6.597 2.6,-6.203
3D body: height 0.36, standoff -0.04, extent 1.401,-6.597 1.8,-6.203
3D body: height 0.36, standoff -0.04, extent -2.599,-6.597 -2.2,-6.203
3D body: height 0.36, standoff -0.04, extent -1.799,-6.597 -1.4,-6.203
3D body: height 0.36, standoff -0.04, extent -0.999,-6.597 -0.6,-6.203
3D body: height 0.36, standoff -0.04, extent -0.199,-6.597 0.2,-6.203
3D body: height 0.36, standoff -0.04, extent 0.601,-6.597 1,-6.203
3D body: height 0.36, standoff -0.04, extent -6.599,-6.597 -6.2,-6.203
3D body: height 0.36, standoff -0.04, extent -5.799,-6.597 -5.4,-6.203
3D body: height 0.36, standoff -0.04, extent -4.999,-6.597 -4.6,-6.203
3D body: height 0.36, standoff -0.04, extent -4.199,-6.597 -3.8,-6.203
3D body: height 0.36, standoff -0.04, extent -3.399,-6.597 -3,-6.203
3D body: height 0.36, standoff -0.04, extent 4.601,-5.797 5,-5.403
3D body: height 0.36, standoff -0.04, extent 3.801,-5.797 4.2,-5.403
3D body: height 0.36, standoff -0.04, extent 3.001,-5.797 3.4,-5.403
3D body: height 0.36, standoff -0.04, extent 2.201,-5.797 2.6,-5.403
3D body: height 0.36, standoff -0.04, extent 1.401,-5.797 1.8,-5.403
3D body: height 0.36, standoff -0.04, extent -2.599,-5.797 -2.2,-5.403
3D body: height 0.36, standoff -0.04, extent -1.799,-5.797 -1.4,-5.403
3D body: height 0.36, standoff -0.04, extent -0.999,-5.797 -0.6,-5.403
3D body: height 0.36, standoff -0.04, extent -0.199,-5.797 0.2,-5.403
3D body: height 0.36, standoff -0.04, extent 0.601,-5.797 1,-5.403
3D body: height 0.36, standoff -0.04, extent -6.599,-5.797 -6.2,-5.403
3D body: height 0.36, standoff -0.04, extent -5.799,-5.797 -5.4,-5.403
3D body: height 0.36, standoff -0.04, extent -4.999,-5.797 -4.6,-5.403
3D body: height 0.36, standoff -0.04, extent -4.199,-5.797 -3.8,-5.403
3D body: height 0.36, standoff -0.04, extent -3.399,-5.797 -3,-5.403
3D body: height 0.36, standoff -0.04, extent 5.401,-5.797 5.8,-5.403
3D body: height 0.36, standoff -0.04, extent 6.201,-5.797 6.6,-5.403
3D body: height 0.36, standoff -0.04, extent 5.401,-6.597 5.8,-6.203
3D body: height 0.36, standoff -0.04, extent 6.201,-6.597 6.6,-6.203
3D body: height 0.36, standoff -0.04, extent 6.201,-4.997 6.6,-4.603
3D body: height 0.36, standoff -0.04, extent 5.401,-4.997 5.8,-4.603
3D body: height 0.36, standoff -0.04, extent 6.201,-4.197 6.6,-3.803
3D body: height 0.36, standoff -0.04, extent 5.401,-4.197 5.8,-3.803
3D body: height 0.36, standoff -0.04, extent 6.201,-3.397 6.6,-3.003
3D body: height 0.36, standoff -0.04, extent 5.401,-3.397 5.8,-3.003
3D body: height 0.36, standoff -0.04, extent 6.201,-2.597 6.6,-2.203
3D body: height 0.36, standoff -0.04, extent 5.401,-2.597 5.8,-2.203
3D body: height 0.36, standoff -0.04, extent 6.201,-1.797 6.6,-1.403
3D body: height 0.36, standoff -0.04, extent 5.401,-1.797 5.8,-1.403
3D body: height 0.36, standoff -0.04, extent 6.201,-0.997 6.6,-0.603
3D body: height 0.36, standoff -0.04, extent 5.401,-0.997 5.8,-0.603
3D body: height 0.36, standoff -0.04, extent 6.201,-0.197 6.6,0.197
3D body: height 0.36, standoff -0.04, extent 5.401,-0.197 5.8,0.197
3D body: height 0.36, standoff -0.04, extent 6.201,0.603 6.6,0.997
3D body: height 0.36, standoff -0.04, extent 5.401,0.603 5.8,0.997
3D body: height 0.36, standoff -0.04, extent 6.201,1.403 6.6,1.797
3D body: height 0.36, standoff -0.04, extent 5.401,1.403 5.8,1.797
3D body: height 0.36, standoff -0.04, extent 6.201,2.203 6.6,2.597
3D body: height 0.36, standoff -0.04, extent 5.401,2.203 5.8,2.597
3D body: height 0.36, standoff -0.04, extent 6.201,3.003 6.6,3.397
3D body: height 0.36, standoff -0.04, extent 5.401,3.003 5.8,3.397
3D body: height 0.36, standoff -0.04, extent 6.201,3.803 6.6,4.197
3D body: height 0.36, standoff -0.04, extent 5.401,3.803 5.8,4.197
3D body: height 0.36, standoff -0.04, extent 6.201,4.603 6.6,4.997
3D body: height 0.36, standoff -0.04, extent 5.401,4.603 5.8,4.997
3D body: height 0.36, standoff -0.04, extent 6.201,5.403 6.6,5.797
3D body: height 0.36, standoff -0.04, extent 5.401,5.403 5.8,5.797
3D body: height 0.36, standoff -0.04, extent 5.401,6.203 5.8,6.597
3D body: height 0.36, standoff -0.04, extent 6.201,6.203 6.6,6.597
3D body: height 0.36, standoff -0.04, extent 4.601,6.203 5,6.597
3D body: height 1.1, standoff 0.3, extent -7.075,-7.075 7.075,7.075
3D body: height 0.36, standoff -0.04, extent 3.801,6.203 4.2,6.597
3D body: height 0.36, standoff -0.04, extent 3.001,6.203 3.4,6.597
3D body: height 0.36, standoff -0.04, extent 2.201,6.203 2.6,6.597
3D body: height 0.36, standoff -0.04, extent 1.401,6.203 1.8,6.597
3D body: height 0.36, standoff -0.04, extent -2.599,6.203 -2.2,6.597
3D body: height 0.36, standoff -0.04, extent -1.799,6.203 -1.4,6.597
3D body: height 0.36, standoff -0.04, extent -0.999,6.203 -0.6,6.597
3D body: height 0.36, standoff -0.04, extent -0.199,6.203 0.2,6.597
3D body: height 0.36, standoff -0.04, extent 0.601,6.203 1,6.597
3D body: height 0.36, standoff -0.04, extent -6.599,6.203 -6.2,6.597
3D body: height 0.36, standoff -0.04, extent -5.799,6.203 -5.4,6.597
3D body: height 0.36, standoff -0.04, extent -4.999,6.203 -4.6,6.597
3D body: height 0.36, standoff -0.04, extent -4.199,6.203 -3.8,6.597
3D body: height 0.36, standoff -0.04, extent -3.399,6.203 -3,6.597
3D body: height 0.36, standoff -0.04, extent -3.399,5.403 -3,5.797
3D body: height 0.36, standoff -0.04, extent -4.199,5.403 -3.8,5.797
3D body: height 0.36, standoff -0.04, extent -4.999,5.403 -4.6,5.797
3D body: height 0.36, standoff -0.04, extent -5.799,5.403 -5.4,5.797
3D body: height 0.36, standoff -0.04, extent -6.599,5.403 -6.2,5.797
3D body: height 0.36, standoff -0.04, extent 0.601,5.403 1,5.797
3D body: height 0.36, standoff -0.04, extent -0.199,5.403 0.2,5.797
3D body: height 0.36, standoff -0.04, extent -0.999,5.403 -0.6,5.797
3D body: height 0.36, standoff -0.04, extent -1.799,5.403 -1.4,5.797
3D body: height 0.36, standoff -0.04, extent -2.599,5.403 -2.2,5.797
3D body: height 0.36, standoff -0.04, extent 1.401,5.403 1.8,5.797
3D body: height 0.36, standoff -0.04, extent 2.201,5.403 2.6,5.797
3D body: height 0.36, standoff -0.04, extent 3.001,5.403 3.4,5.797
3D body: height 0.36, standoff -0.04, extent 3.801,5.403 4.2,5.797
3D body: height 0.36, standoff -0.04, extent 4.601,5.403 5,5.797
3D body: height 0.36, standoff -0.04, extent -3.399,4.603 -3,4.997
3D body: height 0.36, standoff -0.04, extent -4.199,4.603 -3.8,4.997
3D body: height 0.36, standoff -0.04, extent -4.999,4.603 -4.6,4.997
3D body: height 0.36, standoff -0.04, extent -5.799,4.603 -5.4,4.997
3D body: height 0.36, standoff -0.04, extent -6.599,4.603 -6.2,4.997
3D body: height 0.36, standoff -0.04, extent 0.601,4.603 1,4.997
3D body: height 0.36, standoff -0.04, extent -0.199,4.603 0.2,4.997
3D body: height 0.36, standoff -0.04, extent -0.999,4.603 -0.6,4.997
3D body: height 0.36, standoff -0.04, extent -1.799,4.603 -1.4,4.997
3D body: height 0.36, standoff -0.04, extent -2.599,4.603 -2.2,4.997
3D body: height 0.36, standoff -0.04, extent 1.401,4.603 1.8,4.997
3D body: height 0.36, standoff -0.04, extent 2.201,4.603 2.6,4.997
3D body: height 0.36, standoff -0.04, extent 3.001,4.603 3.4,4.997
3D body: height 0.36, standoff -0.04, extent 3.801,4.603 4.2,4.997
3D body: height 0.36, standoff -0.04, extent 4.601,4.603 5,4.997
3D body: height 0.36, standoff -0.04, extent -3.399,3.803 -3,4.197
3D body: height 0.36, standoff -0.04, extent -4.199,3.803 -3.8,4.197
3D body: height 0.36, standoff -0.04, extent -4.999,3.803 -4.6,4.197
3D body: height 0.36, standoff -0.04, extent -5.799,3.803 -5.4,4.197
3D body: height 0.36, standoff -0.04, extent -6.599,3.803 -6.2,4.197
3D body: height 0.36, standoff -0.04, extent 0.601,3.803 1,4.197
3D body: height 0.36, standoff -0.04, extent -0.199,3.803 0.2,4.197
3D body: height 0.36, standoff -0.04, extent -0.999,3.803 -0.6,4.197
3D body: height 0.36, standoff -0.04, extent -1.799,3.803 -1.4,4.197
3D body: height 0.36, standoff -0.04, extent -2.599,3.803 -2.2,4.197
3D body: height 0.36, standoff -0.04, extent 1.401,3.803 1.8,4.197
3D body: height 0.36, standoff -0.04, extent 2.201,3.803 2.6,4.197
3D body: height 0.36, standoff -0.04, extent 3.001,3.803 3.4,4.197
3D body: height 0.36, standoff -0.04, extent 3.801,3.803 4.2,4.197
3D body: height 0.36, standoff -0.04, extent 4.601,3.803 5,4.197
3D body: height 0.36, standoff -0.04, extent -3.399,3.003 -3,3.397
3D body: height 0.36, standoff -0.04, extent -4.199,3.003 -3.8,3.397
3D body: height 0.36, standoff -0.04, extent -4.999,3.003 -4.6,3.397
3D body: height 0.36, standoff -0.04, extent -5.799,3.003 -5.4,3.397
3D body: height 0.36, standoff -0.04, extent -6.599,3.003 -6.2,3.397
3D body: height 0.36, standoff -0.04, extent 0.601,3.003 1,3.397
3D body: height 0.36, standoff -0.04, extent -0.199,3.003 0.2,3.397
3D body: height 0.36, standoff -0.04, extent -0.999,3.003 -0.6,3.397
3D body: height 0.36, standoff -0.04, extent -1.799,3.003 -1.4,3.397
3D body: height 0.36, standoff -0.04, extent -2.599,3.003 -2.2,3.397
3D body: height 0.36, standoff -0.04, extent 1.401,3.003 1.8,3.397
3D body: height 0.36, standoff -0.04, extent 2.201,3.003 2.6,3.397
3D body: height 0.36, standoff -0.04, extent 3.001,3.003 3.4,3.397
3D body: height 0.36, standoff -0.04, extent 3.801,3.003 4.2,3.397
3D body: height 0.36, standoff -0.04, extent 4.601,3.003 5,3.397
3D body: height 0.36, standoff -0.04, extent -3.399,2.203 -3,2.597
3D body: height 0.36, standoff -0.04, extent -4.199,2.203 -3.8,2.597
3D body: height 0.36, standoff -0.04, extent -4.999,2.203 -4.6,2.597
3D body: height 0.36, standoff -0.04, extent -5.799,2.203 -5.4,2.597
3D body: height 0.36, standoff -0.04, extent -6.599,2.203 -6.2,2.597
3D body: height 0.36, standoff -0.04, extent 3.001,2.203 3.4,2.597
3D body: height 0.36, standoff -0.04, extent 3.801,2.203 4.2,2.597
3D body: height 0.36, standoff -0.04, extent 4.601,2.203 5,2.597
3D body: height 0.36, standoff -0.04, extent -3.399,1.403 -3,1.797
3D body: height 0.36, standoff -0.04, extent -4.199,1.403 -3.8,1.797
3D body: height 0.36, standoff -0.04, extent -4.999,1.403 -4.6,1.797
3D body: height 0.36, standoff -0.04, extent -5.799,1.403 -5.4,1.797
3D body: height 0.36, standoff -0.04, extent -6.599,1.403 -6.2,1.797
3D body: height 0.36, standoff -0.04, extent 0.601,1.403 1,1.797
3D body: height 0.36, standoff -0.04, extent -0.199,1.403 0.2,1.797
3D body: height 0.36, standoff -0.04, extent -0.999,1.403 -0.6,1.797
3D body: height 0.36, standoff -0.04, extent -1.799,1.403 -1.4,1.797
3D body: height 0.36, standoff -0.04, extent 1.401,1.403 1.8,1.797
3D body: height 0.36, standoff -0.04, extent 3.001,1.403 3.4,1.797
3D body: height 0.36, standoff -0.04, extent 3.801,1.403 4.2,1.797
3D body: height 0.36, standoff -0.04, extent 4.601,1.403 5,1.797
3D body: height 0.36, standoff -0.04, extent -3.399,0.603 -3,0.997
3D body: height 0.36, standoff -0.04, extent -4.199,0.603 -3.8,0.997
3D body: height 0.36, standoff -0.04, extent -4.999,0.603 -4.6,0.997
3D body: height 0.36, standoff -0.04, extent -5.799,0.603 -5.4,0.997
3D body: height 0.36, standoff -0.04, extent -6.599,0.603 -6.2,0.997
3D body: height 0.36, standoff -0.04, extent 0.601,0.603 1,0.997
3D body: height 0.36, standoff -0.04, extent -0.199,0.603 0.2,0.997
3D body: height 0.36, standoff -0.04, extent -0.999,0.603 -0.6,0.997
3D body: height 0.36, standoff -0.04, extent -1.799,0.603 -1.4,0.997
3D body: height 0.36, standoff -0.04, extent 1.401,0.603 1.8,0.997
3D body: height 0.36, standoff -0.04, extent 3.001,0.603 3.4,0.997
3D body: height 0.36, standoff -0.04, extent 3.801,0.603 4.2,0.997
3D body: height 0.36, standoff -0.04, extent 4.601,0.603 5,0.997
3D body: height 0.36, standoff -0.04, extent -3.399,-0.197 -3,0.197
3D body: height 0.36, standoff -0.04, extent -4.199,-0.197 -3.8,0.197
3D body: height 0.36, standoff -0.04, extent -4.999,-0.197 -4.6,0.197
3D body: height 0.36, standoff -0.04, extent -5.799,-0.197 -5.4,0.197
3D body: height 0.36, standoff -0.04, extent -6.599,-0.197 -6.2,0.197
3D body: height 0.36, standoff -0.04, extent 0.601,-0.197 1,0.197
3D body: height 0.36, standoff -0.04, extent -0.199,-0.197 0.2,0.197
3D body: height 0.36, standoff -0.04, extent -0.999,-0.197 -0.6,0.197
3D body: height 0.36, standoff -0.04, extent -1.799,-0.197 -1.4,0.197
3D body: height 0.36, standoff -0.04, extent 1.401,-0.197 1.8,0.197
3D body: height 0.36, standoff -0.04, extent 3.001,-0.197 3.4,0.197
3D body: height 0.36, standoff -0.04, extent 3.801,-0.197 4.2,0.197
3D body: height 0.36, standoff -0.04, extent 4.601,-0.197 5,0.197
3D body: height 0.36, standoff -0.04, extent -3.399,-0.997 -3,-0.603
3D body: height 0.36, standoff -0.04, extent -4.199,-0.997 -3.8,-0.603
3D body: height 0.36, standoff -0.04, extent -4.999,-0.997 -4.6,-0.603
3D body: height 0.36, standoff -0.04, extent -5.799,-0.997 -5.4,-0.603
3D body: height 0.36, standoff -0.04, extent -6.599,-0.997 -6.2,-0.603
3D body: height 0.36, standoff -0.04, extent 0.601,-0.997 1,-0.603
3D body: height 0.36, standoff -0.04, extent -0.199,-0.997 0.2,-0.603
3D body: height 0.36, standoff -0.04, extent -0.999,-0.997 -0.6,-0.603
3D body: height 0.36, standoff -0.04, extent -1.799,-0.997 -1.4,-0.603
3D body: height 0.36, standoff -0.04, extent 1.401,-0.997 1.8,-0.603
3D body: height 0.36, standoff -0.04, extent 3.001,-0.997 3.4,-0.603
3D body: height 0.36, standoff -0.04, extent 3.801,-0.997 4.2,-0.603
3D body: height 0.36, standoff -0.04, extent 4.601,-0.997 5,-0.603
3D body: height 0.36, standoff -0.04, extent -3.399,-1.797 -3,-1.403
3D body: height 0.36, standoff -0.04, extent -4.199,-1.797 -3.8,-1.403
3D body: height 0.36, standoff -0.04, extent -4.999,-1.797 -4.6,-1.403
3D body: height 0.36, standoff -0.04, extent -5.799,-1.797 -5.4,-1.403
3D body: height 0.36, standoff -0.04, extent -6.599,-1.797 -6.2,-1.403
3D body: height 0.36, standoff -0.04, extent 0.601,-1.797 1,-1.403
3D body: height 0.36, standoff -0.04, extent -0.199,-1.797 0.2,-1.403
3D body: height 0.36, standoff -0.04, extent -0.999,-1.797 -0.6,-1.403
3D body: height 0.36, standoff -0.04, extent -1.799,-1.797 -1.4,-1.403
3D body: height 0.36, standoff -0.04, extent 1.401,-1.797 1.8,-1.403
3D body: height 0.36, standoff -0.04, extent 3.001,-1.797 3.4,-1.403
3D body: height 0.36, standoff -0.04, extent 3.801,-1.797 4.2,-1.403
3D body: height 0.36, standoff -0.04, extent 4.601,-1.797 5,-1.403
3D body: height 0.36, standoff -0.04, extent -3.399,-2.597 -3,-2.203
3D body: height 0.36, standoff -0.04, extent -4.199,-2.597 -3.8,-2.203
3D body: height 0.36, standoff -0.04, extent -4.999,-2.597 -4.6,-2.203
3D body: height 0.36, standoff -0.04, extent -5.799,-2.597 -5.4,-2.203
3D body: height 0.36, standoff -0.04, extent -6.599,-2.597 -6.2,-2.203
3D body: height 0.36, standoff -0.04, extent 3.001,-2.597 3.4,-2.203
3D body: height 0.36, standoff -0.04, extent 3.801,-2.597 4.2,-2.203
3D body: height 0.36, standoff -0.04, extent 4.601,-2.597 5,-2.203
3D body: height 0.36, standoff -0.04, extent -3.399,-3.397 -3,-3.003
3D body: height 0.36, standoff -0.04, extent -4.199,-3.397 -3.8,-3.003
3D body: height 0.36, standoff -0.04, extent -4.999,-3.397 -4.6,-3.003
3D body: height 0.36, standoff -0.04, extent -5.799,-3.397 -5.4,-3.003
3D body: height 0.36, standoff -0.04, extent -6.599,-3.397 -6.2,-3.003
3D body: height 0.36, standoff -0.04, extent 0.601,-3.397 1,-3.003
3D body: height 0.36, standoff -0.04, extent -0.199,-3.397 0.2,-3.003
3D body: height 0.36, standoff -0.04, extent -0.999,-3.397 -0.6,-3.003
3D body: height 0.36, standoff -0.04, extent -1.799,-3.397 -1.4,-3.003
3D body: height 0.36, standoff -0.04, extent -2.599,-3.397 -2.2,-3.003
3D body: height 0.36, standoff -0.04, extent 1.401,-3.397 1.8,-3.003
3D body: height 0.36, standoff -0.04, extent 2.201,-3.397 2.6,-3.003
3D body: height 0.36, standoff -0.04, extent 3.001,-3.397 3.4,-3.003
3D body: height 0.36, standoff -0.04, extent 3.801,-3.397 4.2,-3.003
3D body: height 0.36, standoff -0.04, extent 4.601,-3.397 5,-3.003
3D body: height 0.36, standoff -0.04, extent -3.399,-4.197 -3,-3.803
3D body: height 0.36, standoff -0.04, extent -4.199,-4.197 -3.8,-3.803
3D body: height 0.36, standoff -0.04, extent -4.999,-4.197 -4.6,-3.803
3D body: height 0.36, standoff -0.04, extent -5.799,-4.197 -5.4,-3.803
3D body: height 0.36, standoff -0.04, extent -6.599,-4.197 -6.2,-3.803
3D body: height 0.36, standoff -0.04, extent 0.601,-4.197 1,-3.803
3D body: height 0.36, standoff -0.04, extent -0.199,-4.197 0.2,-3.803
3D body: height 0.36, standoff -0.04, extent -0.999,-4.197 -0.6,-3.803
3D body: height 0.36, standoff -0.04, extent -1.799,-4.197 -1.4,-3.803
3D body: height 0.36, standoff -0.04, extent -2.599,-4.197 -2.2,-3.803
3D body: height 0.36, standoff -0.04, extent 1.401,-4.197 1.8,-3.803
3D body: height 0.36, standoff -0.04, extent 2.201,-4.197 2.6,-3.803
3D body: height 0.36, standoff -0.04, extent 3.001,-4.197 3.4,-3.803
3D body: height 0.36, standoff -0.04, extent 3.801,-4.197 4.2,-3.803
3D body: height 0.36, standoff -0.04, extent 4.601,-4.197 5,-3.803
3D body: height 0.36, standoff -0.04, extent -3.399,-4.997 -3,-4.603
3D body: height 0.36, standoff -0.04, extent -4.199,-4.997 -3.8,-4.603
3D body: height 0.36, standoff -0.04, extent -4.999,-4.997 -4.6,-4.603
3D body: height 0.36, standoff -0.04, extent -5.799,-4.997 -5.4,-4.603
3D body: height 0.36, standoff -0.04, extent -6.599,-4.997 -6.2,-4.603
3D body: height 0.36, standoff -0.04, extent 0.601,-4.997 1,-4.603
3D body: height 0.36, standoff -0.04, extent -0.199,-4.997 0.2,-4.603
3D body: height 0.36, standoff -0.04, extent -0.999,-4.997 -0.6,-4.603
3D body: height 0.36, standoff -0.04, extent -1.799,-4.997 -1.4,-4.603
3D body: height 0.36, standoff -0.04, extent -2.599,-4.997 -2.2,-4.603
3D body: height 0.36, standoff -0.04, extent 1.401,-4.997 1.8,-4.603
3D body: height 0.36, standoff -0.04, extent 2.201,-4.997 2.6,-4.603
3D body: height 0.36, standoff -0.04, extent 3.001,-4.997 3.4,-4.603
3D body: height 0.36, standoff -0.04, extent 3.801,-4.997 4.2,-4.603
3D body: height 0.36, standoff -0.04, extent 4.601,-4.997 5,-4.603
3D body: height 1.11, standoff 1.1, extent -6.697,6.101 -6.1,6.7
